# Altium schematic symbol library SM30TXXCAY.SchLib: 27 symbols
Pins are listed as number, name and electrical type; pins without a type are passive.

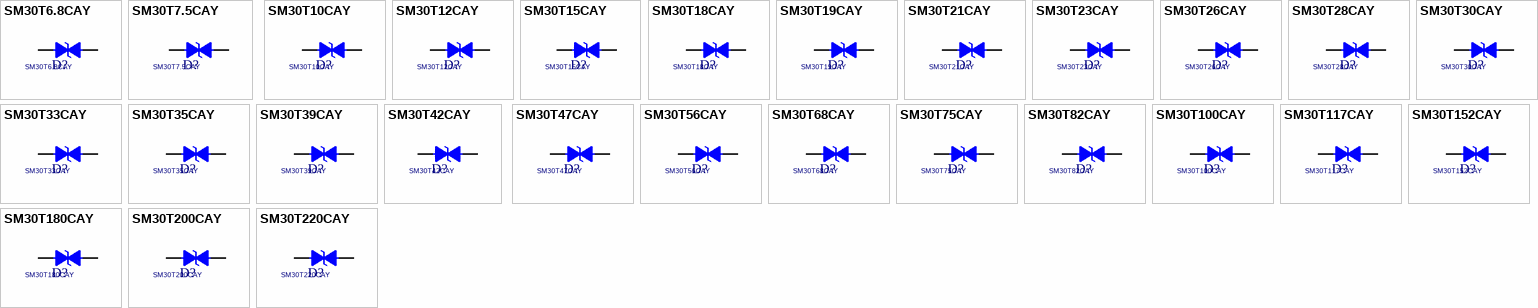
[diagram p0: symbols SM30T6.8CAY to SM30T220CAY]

## SM30T6.8CAY
designator D?
footprint ST_SMCB
pins: 1, 2

## SM30T7.5CAY
designator D?
footprint ST_SMCB
pins: 1, 2

## SM30T10CAY
designator D?
footprint ST_SMCB
pins: 1, 2

## SM30T12CAY
designator D?
footprint ST_SMCB
pins: 1, 2

## SM30T15CAY
designator D?
footprint ST_SMCB
pins: 1, 2

## SM30T18CAY
designator D?
footprint ST_SMCB
pins: 1, 2

## SM30T19CAY
designator D?
footprint ST_SMCB
pins: 1, 2

## SM30T21CAY
designator D?
footprint ST_SMCB
pins: 1, 2

## SM30T23CAY
designator D?
footprint ST_SMCB
pins: 1, 2

## SM30T26CAY
designator D?
footprint ST_SMCB
pins: 1, 2

## SM30T28CAY
designator D?
footprint ST_SMCB
pins: 1, 2

## SM30T30CAY
designator D?
footprint ST_SMCB
pins: 1, 2

## SM30T33CAY
designator D?
footprint ST_SMCB
pins: 1, 2

## SM30T35CAY
designator D?
footprint ST_SMCB
pins: 1, 2

## SM30T39CAY
designator D?
footprint ST_SMCB
pins: 1, 2

## SM30T42CAY
designator D?
footprint ST_SMCB
pins: 1, 2

## SM30T47CAY
designator D?
footprint ST_SMCB
pins: 1, 2

## SM30T56CAY
designator D?
footprint ST_SMCB
pins: 1, 2

## SM30T68CAY
designator D?
footprint ST_SMCB
pins: 1, 2

## SM30T75CAY
designator D?
footprint ST_SMCB
pins: 1, 2

## SM30T82CAY
designator D?
footprint ST_SMCB
pins: 1, 2

## SM30T100CAY
designator D?
footprint ST_SMCB
pins: 1, 2

## SM30T117CAY
designator D?
footprint ST_SMCB
pins: 1, 2

## SM30T152CAY
designator D?
footprint ST_SMCB
pins: 1, 2

## SM30T180CAY
designator D?
footprint ST_SMCB
pins: 1, 2

## SM30T200CAY
designator D?
footprint ST_SMCB
pins: 1, 2

## SM30T220CAY
designator D?
footprint ST_SMCB
pins: 1, 2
